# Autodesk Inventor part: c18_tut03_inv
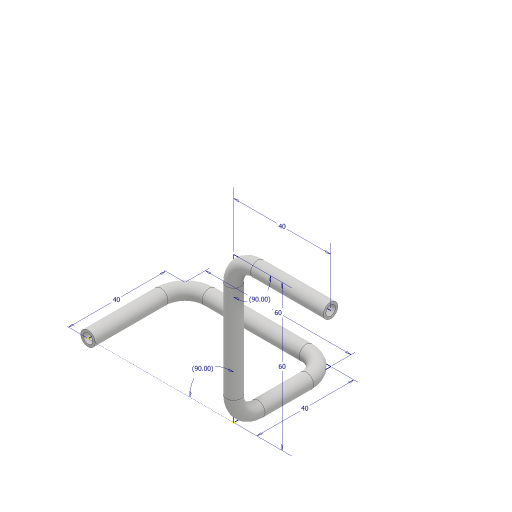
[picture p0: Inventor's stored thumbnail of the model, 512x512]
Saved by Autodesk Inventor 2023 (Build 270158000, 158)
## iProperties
Created: 2017-06
Part Number: c18_tut03_inv
Material: Generic
Document SubType Name: Modeling
Designer: CADCIM 00
Density: 1 g/cm^3
Appearance: Default
Author: CADCIM 00
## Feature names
1. Sweep1
## Parameters: d6 = 90 deg, d8 = 90 deg, d14 = 6 mm, d15 = 4 mm, d16 = 0, d17 = 0
